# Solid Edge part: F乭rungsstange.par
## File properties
Username: bmolnar
Dokumentum tartalom típus: 0
Author: bmolnar
Last saved by: bmolnar
Revision: 79
Sűrűség: 0,000 kg/m^3
Pontosság: 0,990
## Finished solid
Body 1: solid body, 8 faces, 7 edges, 1 vertex.
  Faces by surface: cone 4, cylinder 2, plane 2
  Edges by curve: circle 7
Bounding box of the edges (mm): 6.000 x 6.000 x 45.000, from (-3, -3, -30) to (3, 3, 15).
Cylindrical faces by radius (mm): R1.621 x1, R3 x1
Conical faces (half-angle, radius in mm at the cone's reference point): 45 deg R1.721 x1, 45 deg R2.9 x1, 45 deg R3 x1, 59 deg R0.8105 x1
Planar faces by outward normal: +z 1, -z 1
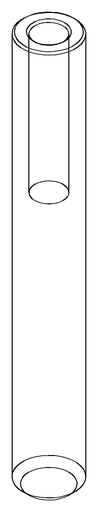
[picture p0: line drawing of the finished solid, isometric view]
